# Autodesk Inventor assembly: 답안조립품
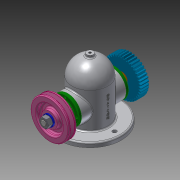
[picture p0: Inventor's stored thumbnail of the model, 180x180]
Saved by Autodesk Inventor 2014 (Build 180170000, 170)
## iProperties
Created: 2019-11
Part Number: 답안조립품
Document SubType Name: Assembly
Designer: OA55
Author: OA55
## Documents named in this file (13)
- C:\Users\OA55\Desktop\491104V1048\답안조립품.iam
- C:\Users\OA55\Desktop\491104V1048\본체.ipt
- C:\Users\OA55\Desktop\491104V1048\커버.ipt
- C:\Users\OA55\Desktop\491104V1048\오일 실 26 38 8.ipt
- C:\Users\OA55\Desktop\491104V1048\베어링 6203.ipt
- C:\Users\OA55\Desktop\491104V1048\축.ipt
- C:\Users\OA55\Desktop\491104V1048\부시.ipt
- C:\Users\OA55\Desktop\491104V1048\키 5x5x12.ipt
- C:\Users\OA55\Desktop\491104V1048\V-벨트풀리.ipt
- V-벨트풀리.ipt
- C:\Users\OA55\Desktop\491104V1048\와셔 12x24.ipt
- C:\Users\OA55\Desktop\491104V1048\너트 M12x1.25.ipt
- C:\Users\OA55\Desktop\491104V1048\스퍼기어.ipt
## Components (1 placed, 1 different names)
1. V-벨트풀리:1 — 각도:4
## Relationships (1: Angle 1)
- 각도:4 [Angle]: V-벨트풀리:1
